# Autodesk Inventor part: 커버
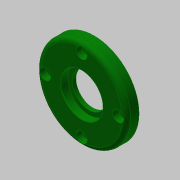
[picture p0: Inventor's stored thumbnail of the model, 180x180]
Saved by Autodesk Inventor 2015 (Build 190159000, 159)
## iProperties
Created: 2019-09
Part Number: 커버
Material: 알루미늄 6061
Document SubType Name: Modeling
Designer: mduedu
Density: 1 g/cm^3
Appearance: 진녹색
Author: mduedu
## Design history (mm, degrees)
sketch "스케치1"
  geometry: C1 r 32 at (0, 0); 1 further point
  constraints: 1 centre point, 1 coincident
  dimensions: "d0" = 64 diameter of C1
extrude "돌출1" new body sketch "스케치1" distance "d1" = 9; taper "d2" = 0 deg
sketch "스케치2"
  geometry: C1 r 21 at (0, 0); 1 further point
  constraints: 1 centre point, 1 coincident
  dimensions: "d3" = 42 diameter of C1
extrude "돌출2" join sketch "스케치2" distance "d4" = 3; taper "d5" = 0 deg
hole "구멍1" diameter "d8" = 24; stored, may be unused: countersink angle "d12" = 90 deg, drill point angle "d14" = 118 deg; dims "d6" = 10, "d7" = 10, "d9" = 6, "d10" = 30, "d11" = 5.2, "d13" = 8
hole "구멍2" diameter "d17" = 37; stored, may be unused: countersink angle "d21" = 90 deg, drill point angle "d23" = 0 deg; dims "d15" = 10, "d16" = 10, "d18" = 6, "d19" = 30, "d20" = 5.2, "d22" = 4
fillet "모깎기1" dims "d24" = 3
fillet "모깎기2" dims "d25" = 3
chamfer "모따기1" distance "d27" = 0.5; stored, may be unused: second distance "d28" = 2, angle "d29" = 30 deg
chamfer "모따기2" distance "d30" = 1; stored, may be unused: second distance "d31" = 2, angle "d32" = 30 deg
sketch "스케치3" dims "d33" = 52
  geometry: 3 further points
  constraints: 2 vertical alignment, 1 coincident, 2 other
hole "구멍3" sketch "스케치3" at (0, 26) diameter "d34" = 4.5; stored, may be unused: countersink angle "d38" = 90 deg, drill point angle "d40" = 0 deg; dims "d35" = 6, "d36" = 8, "d37" = 4.4, "d39" = 4
node "솔리드1"
pattern_circular "원형 패턴1" dims angle "d42" = 360 deg
